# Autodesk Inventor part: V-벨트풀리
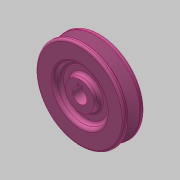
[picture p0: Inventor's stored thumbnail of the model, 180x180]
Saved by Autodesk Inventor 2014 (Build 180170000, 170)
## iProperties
Created: 2019-09
Part Number: V-벨트풀리
Material: 알루미늄 6061
Document SubType Name: Modeling
Designer: mduedu
Density: 1 g/cm^3
Appearance: 분홍색
Author: mduedu
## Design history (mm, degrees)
sketch "스케치1"
  geometry: L1 (-10, 0)-(10, 0); L2 (10, 0)-(10, 43.5); L3 (10, 43.5)-(-10, 43.5); L4 (-10, 43.5)-(-10, 0); L5 (0, 0)-(0, 43.5); L6 (-5.976, 43.5)-(-2.154, 31); L7 (-2.154, 31)-(2.154, 31); L8 (2.154, 31)-(5.976, 43.5); L9 (-10, 39)-(10, 39); 3 further points
  constraints: 18 end point, 8 point on line, 3 perpendicular, 2 midpoint, 2 parallel, 1 coincident, 1 horizontal, 1 other
  dimensions: "d0" = 87 diameter of L3 L1; "d3" = 12.5 distance between parallel lines of L7 L3; "d4" = 34 deg angle of L8 L6; "d5" = 20 distance between parallel lines of L2 L4; "d6" = 8 distance between parallel lines of L9 L7; "d7" = 9.2 distance of point (4.6, 39) point (-4.6, 39)
revolve "회전1" sketch "스케치1" stored, may be unused: angle "d8" = 90 deg
sketch "스케치2"
  geometry: C1 r 14 at (0, 0); C2 r 25 at (0, 0); 1 further point
  constraints: 2 centre point, 2 coincident
  dimensions: "d9" = 28 diameter of C1; "d10" = 50 diameter of C2
extrude "돌출1" cut sketch "스케치2" distance "d11" = 6; taper "d12" = 0 deg
fillet "모깎기1" dims "d13" = 3
fillet "모깎기2" dims "d14" = 3
fillet "모깎기3" dims "d15" = 0.5, "d16" = 1, "d17" = 2
sketch "스케치3"
  geometry: L1 (-2.5, 6.538)-(2.5, 6.538); L2 (2.5, 6.538)-(2.5, 9.3); L3 (2.5, 9.3)-(-2.5, 9.3); L4 (-2.5, 9.3)-(-2.5, 6.538); A1 r 7 centre (0, 0) between (-2.5, 6.538) and (2.5, 6.538); 1 further point
  constraints: 8 end point, 2 parallel, 2 point on circle, 1 centre point, 1 coincident, 1 horizontal, 1 perpendicular
  dimensions: "d18" = 14 diameter of A1; "d20" = 5 distance of L2.end L3.end; "d21" = 16.3 dimension on A1 L3
extrude "돌출2" cut sketch "스케치3" stored distance "d22" = 6; taper "d23" = 0 deg
node "솔리드1"
mirror "대칭1"
